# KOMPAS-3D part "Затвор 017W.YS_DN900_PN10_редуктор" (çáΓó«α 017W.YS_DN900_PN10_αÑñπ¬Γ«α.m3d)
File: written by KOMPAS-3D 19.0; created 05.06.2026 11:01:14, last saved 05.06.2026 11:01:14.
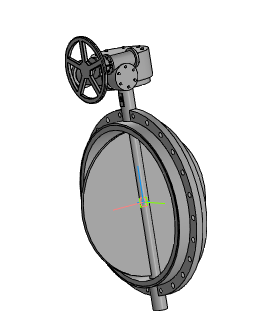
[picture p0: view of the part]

Document properties: Автор: Энергия; Полное имя файла: ..\..\..\3d для проектировщиков\x.x Тип 017W.Y(S) Затвор дисковый поворотный межфланцевый\Затвор 017W.Y(S)_DN50-DN1200_редуктор\Затвор 017W.YS_DN900_PN10_редуктор.a3d

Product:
- Part/product: Затвор 017W.YS_DN900_PN10_редуктор
    Масса: 576.338

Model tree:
1. Операция без истории:1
